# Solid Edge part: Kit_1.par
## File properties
Sűrűség: 0,000 kg/m^3
Pontosság: 0,990
Author: bmolnar
Last saved by: bmolnar
Revision: 77
Username: bmolnar
Dokumentum tartalom típus: 0
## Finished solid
Body 1: solid body, 33 faces, 39 edges, 35 vertices, 2 separate solids.
  Faces by surface: plane 11, cone 10, cylinder 8, torus 4
  Edges by curve: circle 31, line 8
Bounding box of the edges (mm; curved faces can reach further): 19.000 x 18.450 x 3.100, from (-9.5, -9.5, 48.6) to (9.5, 8.95, 51.7).
Cylindrical faces by radius (mm): R4.21 x1, R4.6 x1, R5.68 x1, R5.75 x1, R6.6 x1, R8.5 x1, R8.95 x1, R9.5 x1
Conical faces (half-angle, radius in mm at the cone's reference point): 3 deg R5.715 x1, 7 deg R5.2386 x1, 14 deg R4.105 x1, 14 deg R4.3042 x1, 17 deg R4.105 x1, 23 deg R4.6448 x1, 42.5 deg R4.0959 x1, 45 deg R4.75 x1, 45 deg R6.45 x1, 87 deg R4.0979 x1
Toroidal faces (ring radius, tube radius in mm): R4.5656 r0.1575 x1, R4.974 r0.2275 x1, R5.48 r0.2 x1, R7 r0.4 x1
Planar faces by outward normal: +z 4, -z 5, oblique 2
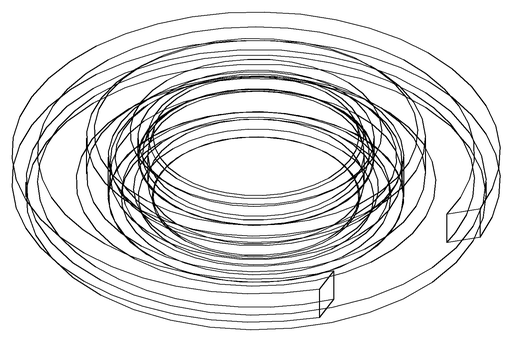
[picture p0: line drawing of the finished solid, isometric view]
